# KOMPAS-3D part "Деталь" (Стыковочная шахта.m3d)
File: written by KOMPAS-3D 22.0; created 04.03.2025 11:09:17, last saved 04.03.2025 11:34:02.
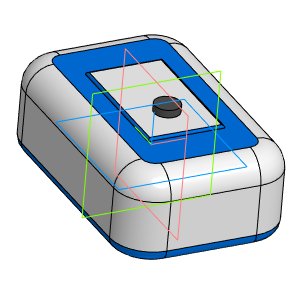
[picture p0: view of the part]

Document properties: Автор: Пользователь Windows; Полное имя файла: C:\Users\Student\Documents\Картошечка\База Сабнатика\Стыковочная шахта\Стыковочная шахта.m3d

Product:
- Body: Тело 1
    Масса: 1.418144
- Part/product: Деталь
    Масса: 1.43151

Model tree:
1. Эскиз:1
2. Элемент выдавливания:1
     Расстояние 1 = 35
3. Скругление:1  (with: Элемент выдавливания:1)
     Радиус = 15
4. Скругление:2  (with: Элемент выдавливания:1)
     Радиус = 10
5. Скругление:3  (with: Элемент выдавливания:1)
     Радиус = 5
6. Эскиз:2  (with: Элемент выдавливания:1)
7. Элемент выдавливания:2
     Расстояние 2 = 12
8. Эскиз:3  (with: Элемент выдавливания:1)
9. Элемент выдавливания:3
     Расстояние 1 = 1
10. Скругление:4  (with: Элемент выдавливания:3)
     Радиус = 1
11. Эскиз:4  (with: Элемент выдавливания:3)
12. Элемент выдавливания:4
     Расстояние 1 = 3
